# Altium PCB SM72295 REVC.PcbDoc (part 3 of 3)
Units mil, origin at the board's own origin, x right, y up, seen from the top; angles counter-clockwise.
Board outline 8660 x 6340 mil, 6 copper layers (Top Layer, MidLayer1, MidLayer2, MidLayer3, MidLayer4, Bottom Layer), stack 118 mil thick; 253 components, 96 nets, 606 pads, 1472 vias.
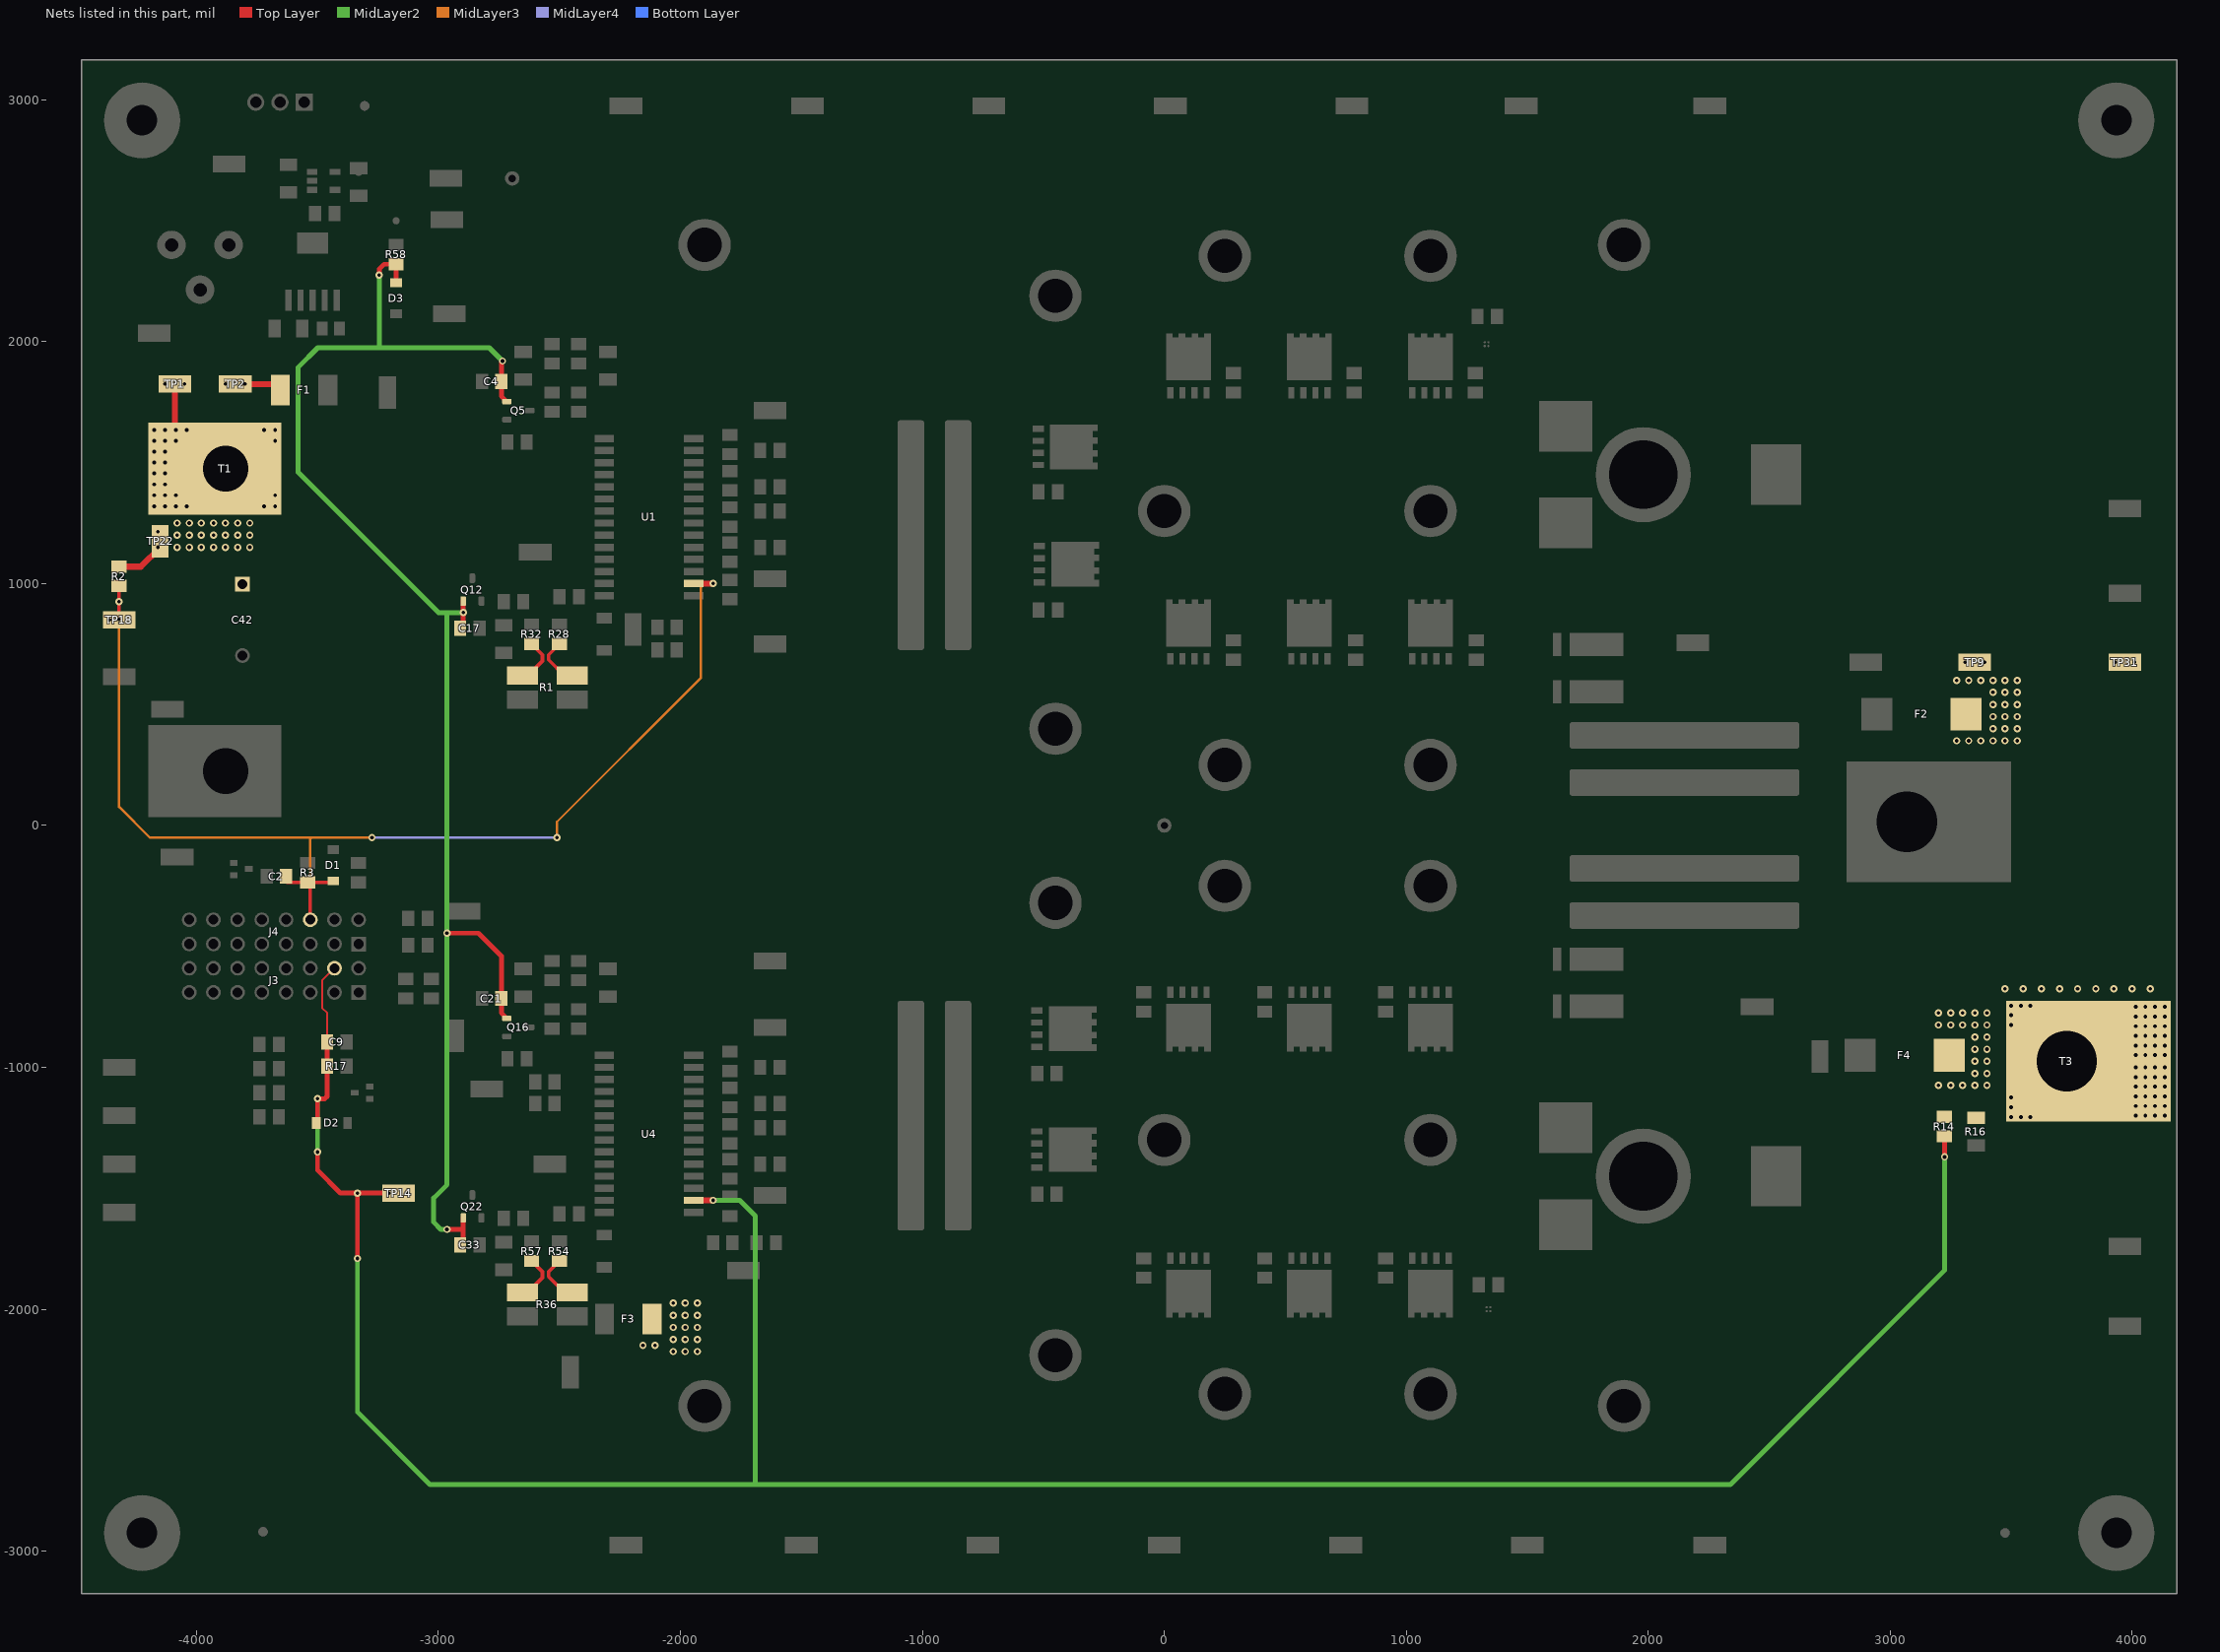
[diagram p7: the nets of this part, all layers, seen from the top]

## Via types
v1: diameter 22, hole 10, Top Layer to Bottom Layer, 518 vias
v2: diameter 30, hole 15, Top Layer to Bottom Layer, 479 vias
v3: diameter 50, hole 28, Top Layer to Bottom Layer, 303 vias
v4: diameter 32, hole 16, Top Layer to Bottom Layer, 172 vias

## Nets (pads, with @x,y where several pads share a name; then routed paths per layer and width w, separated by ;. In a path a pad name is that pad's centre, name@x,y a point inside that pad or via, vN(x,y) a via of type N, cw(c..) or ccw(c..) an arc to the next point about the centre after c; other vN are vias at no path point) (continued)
V12: F2.1 F4.1 R14.2 R16.2 T3.1 TP9.1 TP31.1
  other v2: 3200,-1075 3250,-1075 3300,-1075 3350,-1075 3400,-1075 3350,-1025 3400,-1025 3350,-975 3400,-975 3350,-925 3400,-925 3350,-875 3400,-875 3200,-825 3250,-825 3300,-825 3350,-825 3400,-825 3200,-775 3250,-775 3300,-775 3350,-775 3400,-775 3475,-675 3550,-675 3625,-675 3700,-675 3775,-675 3850,-675 3925,-675 4000,-675 4075,-675 3275,350 3325,350 3375,350 3425,350 3475,350 3525,350 3425,400 3475,400 3525,400 3425,450 3475,450 3525,450 3425,500 3475,500 3525,500 3425,550 3475,550 3525,550 3275,600 3325,600 3375,600 3425,600 3475,600 3525,600 3310,675 3390,675 3930,675 4010,675
  other v4: 3500,-1205 3540,-1205 3580,-1205 4015,-1200 4055,-1200 4095,-1200 4135,-1200 3500,-1165 4015,-1160 4055,-1160 4095,-1160 4135,-1160 3500,-1125 4015,-1120 4055,-1120 4095,-1120 4135,-1120 4015,-1080 4055,-1080 4095,-1080 4135,-1080 4015,-1040 4055,-1040 4095,-1040 4135,-1040 4015,-1000 4055,-1000 4095,-1000 4135,-1000 4015,-950 4055,-950 4095,-950 4135,-950 4015,-910 4055,-910 4095,-910 4135,-910 4015,-870 4055,-870 4095,-870 4135,-870 4015,-830 4055,-830 4095,-830 4135,-830 3500,-825 4015,-790 4055,-790 4095,-790 4135,-790 3500,-785 4015,-750 4055,-750 4095,-750 4135,-750 3500,-745 3540,-745 3580,-745
V12M: C9.1 D2.2 J3.4 R14.1 R17.2 TP14.1 U4.16 | length 11241.4
  Top Layer w8: C9.1@-3460,-865 -3460,-775 -3480.63,-754.37 -3480.63,-640.63 J3.4@-3430,-590
  Top Layer w20: v2(-3500,-1350) -3500,-1425 -3405,-1520 v2(-3335,-1520) ; D2.2@-3500,-1225.53 v2(-3500,-1130) -3470,-1130 -3460,-1120 R17.2@-3460,-995 C9.1@-3460,-895 ; v2(-3335,-1790) v2(-3335,-1520) ; TP14.1@-3165,-1520 -3170,-1520 v2(-3335,-1520) ; v2(3225,-1370.35) R14.1@3225,-1285
  Top Layer w25: U4.16@-1945,-1550 v2(-1865,-1550)
  MidLayer2 w20: v2(-3500,-1350) v2(-3500,-1130) ; v2(-3335,-1790) -3335,-2425 -3035,-2725 -1690,-2725 ; v2(-1865,-1550) -1755,-1550 -1690,-1615 -1690,-2725 ; v2@3224.83,-1370.17 3224.83,-1840.17 2340,-2725 -1690,-2725
  other v2: -3205,-1520 -3125,-1520
V48: C42.1 F1.2 F3.2 R2.2 T1.1 TP1.1 TP2.1 TP22.1 | length 836.3
  Top Layer w20: T1.1@-3920,1435 T1.1@-3880,1475
  Top Layer w25: R2.2@-4330,1070 -4230,1070 -4150,1150 TP22.1@-4150,1175 TP22.1@-4150,1200 ; T1.1@-4090,1495 TP1.1@-4090,1825 ; TP2.1@-3840,1825 F1.2@-3653.43,1825
  other v2: -2030,-2175 -1980,-2175 -1930,-2175 -2155,-2150 -2105,-2150 -2030,-2125 -1980,-2125 -1930,-2125 -2030,-2075 -1980,-2075 -1930,-2075 -2030,-2025 -1980,-2025 -1930,-2025 -2030,-1975 -1980,-1975 -1930,-1975 -4160,1150 -4080,1150 -4030,1150 -3980,1150 -3930,1150 -3880,1150 -3830,1150 -3780,1150 -4080,1200 -4030,1200 -3980,1200 -3930,1200 -3880,1200 -3830,1200 -3780,1200 -4160,1215 -4080,1250 -4030,1250 -3980,1250 -3930,1250 -3880,1250 -3830,1250 -3780,1250 -4130,1825 -4050,1825 -3880,1825 -3800,1825
  other v4: -4175,1320 -4130,1320 -4085,1320 -4040,1320 -3720,1320 -3675,1320 -4175,1365 -4130,1365 -4085,1365 -3675,1365 -4175,1410 -4130,1410 -4175,1455 -4130,1455 -4175,1500 -4130,1500 -4175,1545 -4130,1545 -4175,1590 -4130,1590 -4085,1590 -3675,1590 -4175,1635 -4130,1635 -4085,1635 -4040,1635 -3720,1635 -3675,1635
V48_1_N: R1.3 R32.2 | length 197.2
  Top Layer w15: R1.3@-2653.35,619.21 -2630.79,619.21 -2570,680 -2570,705 R32.2@-2615,750
V48_1_P: R1.4 R28.2 | length 209.2
  Top Layer w15: R28.2@-2500,750 -2545,705 -2545,685 -2479.21,619.21 R1.4@-2446.65,619.21
V48_2_N: R36.3 R57.2 | length 197.2
  Top Layer w15: R36.3@-2653.35,-1930.79 -2630.79,-1930.79 -2570,-1870 -2570,-1845 R57.2@-2615,-1800
V48_2_P: R36.4 R54.2 | length 209.2
  Top Layer w15: R54.2@-2500,-1800 -2545,-1845 -2545,-1865 -2479.21,-1930.79 R36.4@-2446.65,-1930.79
V48M: C2.1 D1.2 J4.6 R2.1 R3.2 TP18.1 U1.16 | length 4960.7
  Top Layer w10: D1.2@-3440.53,-235 D1.2@-3435,-229.47
  Top Layer w15: TP18.1@-4320,850 v2(-4320,925) R2.1@-4320,990 ; C2.1@-3625,-235 R3.2@-3540,-235 D1.2@-3440.53,-235 ; J4.6@-3530,-390 R3.2@-3530,-245
  Top Layer w25: U1.16@-1945,1000 v2(-1865,1000)
  MidLayer3 w10: v2(-4320,925) -4320,76.75 -4193.25,-50 -3525,-50 ; J4.6@-3530,-390 -3530,-55 -3525,-50 ; v2(-3275,-50) -3525,-50 ; v2(-2510,-50) -2510,15 -1915,610 -1915,985 -1900,1000 v2(-1865,1000)
  MidLayer4 w10: v2(-3275,-50) v2(-2510,-50)
  Bottom Layer w8: J4.6@-3530,-390 J4.6@-3517.11,-390
  other v2: -4360,850 -4319.85,851.47
ZERO_BIAS: C4.1 C17.1 C21.1 C33.1 D3.2 Q5.1 Q12.1 Q16.1 Q22.1 R58.2 | length 6331.5
  Top Layer w20: v2(-3245,2275) -3245,2300 -3225,2320 R58.2@-3175,2320 D3.2@-3175,2244.47 ; v2(-2965,-1670) -2902.4,-1670 -2897.4,-1665 ; v2(-2965,-445) -2835,-445 -2740,-540 C21.1@-2740,-715 -2740,-774.84 Q16.1@-2717.24,-797.6 ; C33.1@-2897.4,-1732.4 -2897.4,-1665 ; Q22.1@-2897.4,-1622.24 -2897.4,-1665 ; C17.1@-2897.4,832.6 v2(-2897.4,880) Q12.1@-2897.4,927.76 ; v2(-2735,1920) -2740,1915 C4.1@-2740,1835 -2740,1775.16 Q5.1@-2717.24,1752.4
  MidLayer2 w20: v2(-3245,2275) -3245,1975 ; v2(-2965,-1670) -2990,-1670 -3020,-1640 -3020,-1540 -2965,-1485 v2(-2965,-445) -2965,879 ; v2(-2897.4,880) -3000,880 -3580,1460 -3580,1893.8 -3498.8,1975 -3245,1975 ; v2(-2735,1920) -2790,1975 -3245,1975
pads on no net: FID1.1 FID2.1 FID3.1 FID4.1 FID5.1 FID6.1 H1.1 H2.1 H3.1 H4.1 H9. H10. H11. H12. H13. H14. H15. H16. H17. H18. H19. H20. H21. H22. H23. H24. H25. H26. H27. H28. H50.1 H51.1 H64.0 J2.1 J3.1 J3.3 J3.10 J3.12 J3.13 J3.14 J3.15 J3.16 J4.3 J4.7 J4.8 J4.10 J4.12 J4.15 L1.3 L2.3 U1.4 U1.11 U4.4 U4.11

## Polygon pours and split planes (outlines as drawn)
NetF3_1 on Top Layer "Top Layer-NetF3_1" (solid, remove dead copper, pour order 72): -2515,-1930 -2515,-2160 -2270,-2160 -2270,-1930
GND on Top Layer "Top Layer-GND" (solid, remove dead copper, pour order 111): -4448.96,-3152.54 -4448.96,3192.46 4211.04,3192.46 4211.04,-3152.54
NetC19_2 on Top Layer " Top Layer-Net C18_2" (solid, remove dead copper, pour order 68): -3105,-1920 -2595,-1920 -2595,-2176.5 -3105,-2176.5
NetF1_1 on Top Layer "Top Layer-Net F1_1" (solid, remove dead copper, pour order 74): -3175,1625 -3175,1915 -3535,1915 -3535,1625
NetC1_2 on Top Layer "Top Layer-NetC1_2" (solid, remove dead copper, pour order 61): -2595,625 -2855,625 -2855,400 -2594.84,400
HG2A_N on Top Layer "Top Layer-SWN_2" (solid, remove dead copper, pour order 109): -480,-745 -480,-1625 -136.03,-1810 -35,-1811.33 1550,-1811.33 1550,-1995 2300,-1995 2300,-1400 1520,-1400 1520,-745
NetC19_2 on Top Layer "Top Layer-C18_2" (solid, remove dead copper, pour order 69): -1550,-2680 1525,-2680 1525,-1835 820,-1835 820,-1840 660,-1840 660,-1835 240,-1835 240,-1835.51 98.62,-1835 -125,-1835 -405,-1695 -1550,-1695
NetC1_2 on Top Layer "Top Layer-NETC1_2" (solid, pour order 62): 1525,2675 1525,1830 -40,1835 -450,1710 -1510,1710 -1510,2675
NetC1_2 on Top Layer "Top Layer-NETC1_2" (solid, remove dead copper, pour order 64): -965,660 -1505,660 -1505,2005.69 -1509.31,2010 -970,2010
HG1A_N on Top Layer "Top Layer-SWN_1" (solid, pour order 108): -105,730 -475,955 -480,1695 -70,1820 1300,1810 1550,1810 1550,2000 2300,2000 2300,1375 1525,1375 1525,1200 1525,735
NetC19_2 on Top Layer "Top Layer-NETC18_2" (solid, remove dead copper, pour order 70): -970,-660 -1535,-660 -1540,-655 -1547.58,-662.58 -1547.58,-1665 -1550,-1975 -970,-1975
V48 on Top Layer "Top Layer-V48" (solid, remove dead copper, pour order 88): -4205,1915 -4205,875 -3545,875 -3545,1915
V12 on Top Layer "Top Layer-V2" (solid, remove dead copper, pour order 110): 3550,310 3550,-290 3160,-290 3160,-1235 4150,-1235 4150,725 3240,725 3240,310
V48 on Top Layer "Top Layer-V48" (solid, remove dead copper, pour order 76): -2190.49,-1930 -1910,-1930 -1912.65,-2230 -2190.49,-2230
NetF1_1 on Top Layer "Top Layer-NetF1_1" (solid, remove dead copper, pour order 71): -2509,625 -2255.94,625 -2255.94,390 -2509,390
NetL1_2 on Top Layer "Top Layer-NETL1_2" (solid, remove dead copper, pour order 90): 1550,1355 1550,825 1675,825 1675,670 2300,670 2300,1355
NetC8_2 on Top Layer "Top Layer-NETC7_2" (solid, remove dead copper, pour order 66): 1670,320 1670,625 3035,625 3035,320
NetC24_2 on Top Layer "Top Layer-NETC13_2" (solid, remove dead copper, pour order 67): 1675,-625 1675,-320 2960,-320 2960,-1080 2618.7,-1080 2618.7,-625
NetL2_1 on Top Layer "Top Layer-NETL2_1" (solid, remove dead copper, pour order 92): 1550,-1355 1550,-815 1675,-815 1675,-670 2540,-670 2540,-1185 2300,-1185 2300,-1355
NetL1_2 on MidLayer3 "MidLayer3-NET L1_2" (solid, remove dead copper, pour order 84): 1575,1340 1575,835 2265,835 2265,1340
NetL2_1 on MidLayer3 "MidLayer3-NET L2_1" (solid, pour order 77): 1580,-845 1580,-1335 2260,-1335 2260,-845
NetC19_2 on MidLayer3 "MidLayer3-NetC18_2" (solid, remove dead copper, pour order 133): -50,-1835 -50,-2050 -45,-2055 1220,-2055 1220,-1840 1225,-1835
NetC24_2 on MidLayer3 "MidLayer3-NetC23_2" (solid, remove dead copper, pour order 138): 2960,-320 2960,-1080 2618.7,-1080 2618.7,-625 1670,-625 1670,-325 1675,-320
NetC8_2 on MidLayer3 "MidLayer3-NetC8_2" (solid, remove dead copper, pour order 139): 3035,625 1670,625 1670,320 3035,320
V12 on MidLayer3 "MidLayer3-V12" (solid, remove dead copper, pour order 132): 4185,725 3240,725 3240,310 3550,310 3550,-290 3160,-290 3160,-1230 3155,-1235 4185,-1235
V48 on MidLayer3 "MidLayer3-V48" (solid, remove dead copper, pour order 135): -4155,1300 -3680,1300 -3680,1100 -2555,55 -2555,-1321.83 -1885,-1776.83 -1885,-2205 -2390,-2205 -2390,-1895 -2930,-1895 -2930,-325 -4155,810
NetC19_2 on MidLayer3 "MidLayer3-NetC18_2" (solid, remove dead copper, pour order 136): -3130,-1915 -2580,-1915 -2580,-2475 -2555,-2500 -1455,-2500 -1455,-650 -1130,-650 -1130,-2637.5 -1362.5,-2870 -2750,-2870 -3130,-2660
HG2A_N on MidLayer3 "MidLayer3-SWN2" (solid, remove dead copper, pour order 140): 2300,-1400 1525.47,-1400 1520,-1394.53 1520,-730 -490,-730 -490,-1610 -470,-1625 -140,-1820 1555,-1820 1563.59,-1828.59 1563.59,-1999.22 2298.03,-1999.22 2300,-2001.18
HG1A_N on MidLayer3 "MidLayer3-SWN1" (solid, remove dead copper, pour order 137): 2300,1380.49 2300,2001.18 1551.18,2001.18 1550,2000 1550,1820 -70,1820 -480,1695 -479.88,1677.8 -480,945 -318.68,859.94 -105,730 -85,730 1526.72,736.72 1526.72,1380.49
GND on MidLayer3 "MidLayer3-GND" (solid, remove dead copper, pour order 141): -4500,-3175 -4500,3200 4200,3200 4200,-3175
NetC1_2 on MidLayer3 "MidLayer3-NetC1_2" (solid, remove dead copper, pour order 134): -30,1835 1235,1835 1235,2070 -24.65,2070 -30,2064.65
NetL1_2 on Bottom Layer "Bottom Layer-NET L1_2" (solid, remove dead copper, pour order 150): 1560,1345 1560,825 2270,825 2270,1345
NetL2_1 on Bottom Layer "Bottom Layer-NET L2_1" (solid, pour order 154): 1571.29,-827.51 1571.29,-1333.84 1575.5,-1338.05 2297.49,-1338.05 2297.49,-830.02 2300,-827.51
NetL2_1 on Bottom Layer "Bottom Layer-Net L2_1" (solid, remove dead copper, pour order 151): 1571.29,-825 1571.29,-1338.05 2300,-1338.05 2300,-825
NetC19_2 on Bottom Layer "Bottom Layer-NetC18_2" (solid, remove dead copper, pour order 152): -25,-1836.82 -25,-2050 1222.49,-2050 1225,-2047.49 1222.49,-2044.98 1222.49,-1835
NetC24_2 on Bottom Layer "Bottom Layer-NetC23_2" (solid, remove dead copper, pour order 173): 2960,-320 2960,-1080 2618.7,-1080 2618.7,-625 1650,-625 1650,-345 1675,-320
NetC8_2 on Bottom Layer "Bottom Layer-NetC8_2" (solid, remove dead copper, pour order 153): 3035,625 1660,625 1675,610 1675,325 3030,325 3035,320
V12 on Bottom Layer "Bottom Layer-V12" (solid, remove dead copper, pour order 155): 4185,725 3240,725 3240,310 3550,310 3550,-290 3160,-290 3160,-1235 4185,-1235
HG2A_N on Bottom Layer "Bottom Layer-SWN2" (solid, remove dead copper, pour order 161): 2300,-2001.18 2300,-1400 1525.47,-1400 1525.47,-739.53 1526.14,-730 -489.92,-730 -490.58,-1613.81 -474.39,-1630 -115,-1820 -105,-1825 1555,-1820 1555,-1960 1552.07,-1995.06 1560,-2005 1555,-2010 2305,-2005
HG1A_N on Bottom Layer "Bottom Layer-SWN1" (solid, remove dead copper, pour order 158): 2305,2001.18 1551.18,2001.18 1550,2000 1550.83,1999.17 1550.83,1819.62 -70.82,1819.62 -255,1765 -475,1695 -471.29,952.74 -105,730 1516.89,730 1518.44,728.44 1525,735 1525,1378.38 2308.38,1378.38 2310,1380
NetC19_2 on Bottom Layer "Bottom Layer-NETC18_2" (solid, remove dead copper, pour order 156): -1600,-640 -1100,-640 -1100,-1050 -1600,-1050
NetF1_1 on Bottom Layer "Bottom Layer-NetF1_1" (solid, remove dead copper, pour order 163): -2515.68,625.68 -2515,625 -2285,625 -2285,385 -2285.68,384.32 -2515.68,384.32
NetC1_2 on Bottom Layer "Bottom Layer-NetC1_2" (solid, remove dead copper, pour order 148): -2855,625 -2595,625 -2595,400 -2855,400
V48 on Bottom Layer "Bottom Layer-V48" (solid, remove dead copper, pour order 167): -4200,1665 -4199,1666 -3650,1666 -3650,1125 -4195.08,1125 -4199.9,1129.83
NetF1_1 on Bottom Layer "Bottom Layer-NetF1_1" (solid, remove dead copper, pour order 165): -3480,1915 -3265,1915 -3265,1625 -3265.06,1625.06 -3480,1625
NetC19_2 on Bottom Layer "Bottom Layer-NetC18_2" (solid, remove dead copper, pour order 157): -3105,-2176.5 -2595,-2176.5 -2596.22,-2175.28 -2596.22,-1920 -3103.78,-1920 -3105,-1921.22
V48 on Bottom Layer "Bottom Layer-V48" (solid, remove dead copper, pour order 169): -2165,-1930 -1910,-1930 -1912.41,-1932.41 -1912.41,-2215 -2162.72,-2215 -2165,-2212.72
GND on Bottom Layer "Bottom Layer-GND" (solid, remove dead copper, pour order 177): -4483,-3200 -4483,3200 4160,3200 4160,-3200
NetC1_2 on Bottom Layer "Bottom Layer-NetC1_2" (solid, remove dead copper, pour order 171): -1506,680 -1505,681 -1093,681 -1091,683 -1091,1134 -1502.49,1134 -1505,1136.51
NetC1_2 on Bottom Layer "Bottom Layer-NetC1_2" (solid, pour order 149): -30,2070 -30,1835 1235,1835 1235,2070 -30,2070
GND on MidLayer1 "MidLayer1-GND" (solid, remove dead copper, pour order 121): -4500,-3150 -4500,3175 4200,3175 4200,-3150
NetL1_2 on MidLayer1 "MidLayer1-NET L1_2" (solid, remove dead copper, pour order 80): 1580,1340 1580,830 2260,830 2260,1340
NetL2_1 on MidLayer1 "MidLayer1-NET L2_1" (solid, remove dead copper, pour order 73): 1560,-845 1560,-1330 2255,-1330 2255,-845
NetC19_2 on MidLayer1 "MidLayer1-NetC18_2" (solid, remove dead copper, pour order 112): -25,-1835 -25,-2050 1225,-2050 1225,-1835
NetC24_2 on MidLayer1 "MidLayer1-NetC23_2" (solid, remove dead copper, pour order 118): 2960,-320 2960,-1080 2630,-1080 2625,-1075 2618.7,-1068.7 2618.7,-625 1665,-625 1675,-615 1675,-320
NetC8_2 on MidLayer1 "MidLayer1-NetC8_2" (solid, remove dead copper, pour order 119): 3035,625 1670,625 1670,320 3035,320
V12 on MidLayer1 "MidLayer1-V12" (solid, remove dead copper, pour order 114): 4185,725 3240,725 3240,310 3550,310 3550,-290 3160,-290 3160,-1232.93 3162.07,-1235 4200,-1235
NetC19_2 on MidLayer1 "MidLayer1-NetC18_2" (solid, remove dead copper, pour order 115): -3105,-1920 -2596.22,-1920 -2595,-1921.22 -2595,-2176.5 -3101.5,-2176.5 -3105.66,-2180.66
HG2A_N on MidLayer1 "MidLayer1-SWN2" (solid, remove dead copper, pour order 120): 2305,-2001.18 2300,-1996.18 2300,-1400 1525.47,-1400 1520,-1394.53 1520,-745 -470,-745 -480,-735 -480,-1624.39 -225.61,-1624.39 -40,-1810 -38.67,-1811.33 1550,-1811.33 1550,-1990 1545,-1995
HG1A_N on MidLayer1 "MidLayer1-SWN1" (solid, remove dead copper, pour order 117): 2300,1380.49 2300,2001.18 1551.18,2001.18 1550,2000 1550,1825 -60,1825 -200,1785 -480,1695 -480,955 -465,945 -455,935 -325.31,863.97 -105.47,730.28 1525,730.28 1525,1378.38 1524.8,1378.57 1526.72,1380.49
NetC1_2 on MidLayer1 "MidLayer1-NetC1-2" (solid, remove dead copper, pour order 113): -30,2070 1235,2070 1235,1835 -30,1835
NetL1_2 on MidLayer4 "MidLayer4-NET L1_2" (solid, remove dead copper, pour order 86): 1571.29,1338.05 1571.29,825 2265,825 2265,1338.05
NetL2_1 on MidLayer4 "MidLayer4-NET L2_1" (solid, pour order 78): 1570,-830 1570,-1338.05 2268.71,-1338.05 2268.71,-833.71 2265,-830
NetC19_2 on MidLayer4 "MidLayer4-NetC18_2" (solid, remove dead copper, pour order 144): -25,-1836.82 -25,-2050 -22.49,-2047.49 1225,-2047.49 1225,-1836.82
V12 on MidLayer4 "MidLayer4-V12" (solid, remove dead copper, pour order 143): 4185,725 3240,725 3240,310 3550,310 3550,-290 3160,-290 3160,-1235 4185,-1235
HG1A_N on MidLayer4 "MidLayer4-SWN1" (solid, remove dead copper, pour order 145): 2300,1380.49 2300,2001.18 2298.82,2000 1550,2000 1551.18,1998.82 1550,1825 1537.36,1825 -40,1830 -480,1695 -480,955 -339.03,872.31 -105,730 1526.72,730 1526.72,1380.49
HG2A_N on MidLayer4 "MidLayer4-SWN2" (solid, remove dead copper, pour order 146): 2300,-1400 1525.47,-1400 1525.47,-735.47 1523.7,-733.7 -484.97,-733.7 -490,-1610 -490,-1620 -135,-1810 1534.44,-1810 1545,-2000 1545.78,-1999.22 2300,-1994.03
GND on MidLayer4 "MidLayer4-GND" (solid, remove dead copper, pour order 147): -4500,-3160 -4500,3200 4200,3200 4200,-3160
NetC1_2 on MidLayer4 "MidLayer4-NetC1_2" (solid, remove dead copper, pour order 142): -30,2070 -30,1835 1230,1835 1235,1840 1235,2070 -26.03,2070 -30,2066.03
NetL1_2 on MidLayer2 "MidLayer2-NET L1_2" (solid, remove dead copper, pour order 82): 1569.31,1345 1569.31,815 2305,815 2305,1345
NetL2_1 on MidLayer2 "MidLayer2-NET L2_1" (solid, remove dead copper, pour order 75): 1560,-830 1560,-1335 2267.15,-1335 2267.15,-830
NetC19_2 on MidLayer2 "MidLayer2-NetC18_2" (solid, remove dead copper, pour order 122): -25,-1835 -25,-2050 1225,-2050 1225,-1835
NetC19_2 on MidLayer2 "MidLayer2-NetC18_2" (solid, remove dead copper, pour order 123): -1445,-645 -1445,-945 -1311.45,-1078.55 -1130.25,-1078.55 -1130.25,-658.92 -1130,-645
NetC24_2 on MidLayer2 "MidLayer2-NetC23_2" (solid, remove dead copper, pour order 128): 2960,-320 2960,-1080 2618.7,-1080 2618.7,-625 1660,-625 1670,-615 1670,-325
V12 on MidLayer2 "MidLayer2-V12" (solid, remove dead copper, pour order 125): 4185,725 3240,725 3240,310 3550,310 3550,-290 3160,-290 3162.07,-292.07 3162.07,-1235 4185,-1235
NetC1_2 on MidLayer2 "MidLayer2-NetC1_2" (solid, remove dead copper, pour order 126): -1505,1100 -1115,1100 -1115,495 -1475,90 -2905,90 -2905,650 -2575,650 -2574.61,635.25 -2574.61,373.27 -2572.87,375 -1830,375 -1505,700
HG2A_N on MidLayer2 "MidLayer2-SWN2" (solid, remove dead copper, pour order 130): 2298.97,-1995.06 2300,-1994.03 2300,-1400 1520,-1400 1520,-735 -480,-735 -480,-1625 -285,-1730 -135,-1810 1550,-1811.33 1550,-1990 1551.65,-1994.04 1560,-1995 2300,-1995
HG1A_N on MidLayer2 "MidLayer2-SWN1" (solid, pour order 129): 2300,1380.49 2300,2001.18 1550,2000 1550,1810 -55,1820 -71.26,1819.62 -480,1695 -480,970 -105,730 1518.44,728.44 1526.72,736.72 1526.72,1380.49
GND on MidLayer2 "MidLayer2-GND" (solid, remove dead copper, pour order 131): -4500,-3170 -4500,3200 4200,3200 4200,-3170
NetC1_2 on MidLayer2 "MidLayer2-NetC1_2" (solid, remove dead copper, pour order 124): -30,1835 1235,1835 1235,2070 1225,2060 -30,2060
NetF1_1 on MidLayer2 "MidLayer2-NetF1_1" (solid, remove dead copper, pour order 127): -2255,375 -2255,850 -3080,1675 -3080,1913 -3142.01,1912.99 -3517,1912.99 -3517,1613 -3517.02,1607.06 -2529.59,645.49 -2530,375

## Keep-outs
Keep-Out Layer:
  the board outline again, w10
  text ".Layer_Name" at -4298,-4033.49 h60

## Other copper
Top Layer:
  text ".Layer_Name" at -4298,-4033.49 h60
MidLayer1:
  rectangle net V48: -2183.02,-2230.74 -1905,-1925
  rectangle net NetF3_1: -2510,-2170 -2375,-1930
  rectangle net NetC19_2: -1460,-1055 -1140,-655
  rectangle net NetC1_2: -1455,700 -1150,1110
  rectangle net NetF1_1: -3499,1625.08 -3265,1915
  rectangle net V48: -4125,1100 -3733,1295
  rectangle net NetC1_2: -2853.53,395 -2595,628.53
  rectangle net NetF1_1: -2510,387 -2250,625
  rectangle net NetL1_2: 1675,670 1910,840
  rectangle net NetC8_2: 1675,475 1910,625
  rectangle net NetL2_1: 1660,-850 1925,-670
  rectangle net NetC24_2: 1660,-625 1925,-470
MidLayer2:
  rectangle net V48: -4125,1100 -3733,1305
  rectangle net V48: -2184.75,-2234.46 -1905,-1925
  rectangle net NetF3_1: -2510,-2170 -2365,-1930
  rectangle net NetC19_2: -3129.51,-2185 -2590,-1915.1
  rectangle net NetL1_2: 1655,670 1930,825
  rectangle net NetC8_2: 1655,505 1930,625
  rectangle net NetL2_1: 1660,-840 1930,-670
  rectangle net NetC24_2: 1660,-625 1930,-475
MidLayer3:
  rectangle net NetF1_1: -3499,1620 -3260,1915
  rectangle net NetF1_1: -2508.16,390 -2255.94,631.45
  rectangle net NetC1_2: -2855,395 -2595,625
  rectangle net NetC1_2: -1465,685 -1145,1105
  rectangle net NetF3_1: -2510,-2170 -2375,-1930
  rectangle net NetL1_2: 1670,670 1910,865
  rectangle net NetC8_2: 1670,475 1910,625
  rectangle net NetL2_1: 1670,-865 1915,-665
  rectangle net NetC24_2: 1670,-625 1915,-490
MidLayer4:
  rectangle net V48: -4135,1090 -3720,1310
  rectangle net NetF1_1: -2509,387 -2250,625
  rectangle net NetC1_2: -2855,395 -2595,625
  rectangle net NetC19_2: -1455,-1090 -1145,-640
  rectangle net NetC1_2: -1455,700 -1150,1110
  rectangle net V48: -2175,-2210.91 -1886.92,-1935
  rectangle net NetF3_1: -2500,-2160 -2370,-1930
  rectangle net NetC19_2: -3103.78,-2190 -2595,-1920
  rectangle net NetL2_1: 1660,-840 1935,-670
  rectangle net NetC24_2: 1660,-625 1935,-485
  rectangle net NetL1_2: 1660,670 1925,835
  rectangle net NetC8_2: 1660,470 1925,625
  rectangle net NetC8_2: 2775,305 3065,610
Bottom Layer:
  rectangle net NetL1_2: 1660,670 1925,835
  rectangle net NetC8_2: 1660,470 1925,625
  rectangle net NetL2_1: 1665,-845 1925,-670
  rectangle net NetC24_2: 1665,-625 1925,-470
  rectangle net P2_LOW: -4390,-1235 -4250,-1165
  rectangle net P2_HI: -4390,-1435 -4250,-1365
  rectangle net V48: -4160,1790.06 -4017.33,1860
  rectangle net V48: -3912.67,1789.56 -3768.54,1859.94
  rectangle net NetF1_1: -3245.98,1719.29 -3174.37,1860.44
  rectangle net HG1A_N: -1700,1680.06 -1560,1749.94
  rectangle net NetL1_2: 2115,720 2255,790
  rectangle net NetC8_2: 2830,640 2970,710
  rectangle net V12M: -3235,-1555 -3095,-1485
  rectangle net \O\V\P: -1810,-1880 -1670,-1805
  rectangle net V48M: -4388,812 -4299,884.94
  rectangle net P1_HI: -4390,580.06 -4299.48,652
  rectangle net NetF3_1: -2490,-2330 -2420,-2190
  rectangle net P1_LO: -4190,440 -4050,515
  rectangle net HG2A_N: -1700,-869.94 -1625.49,-800
  rectangle net LG2A: -1700,-595 -1560,-525
  rectangle net 12V: -3935,2700 -3795,2770
  text ".Layer_Name" at -4298,-4033.49 h60

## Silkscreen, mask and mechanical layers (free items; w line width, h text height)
Top Overlay:
  lines w10: -4090,-3060.16 -4090,-3140 -4090,-3145 -3270,-3145 -3270,-1275 ; -4090,-2760 -4090,-320 -3265,-320 -3270,-325 ; -3270.71,-1040 -3270.71,-738.21
  text "SM72295" at 3120,2470 h100
  text "TIDA-00558" at 2975,2300 h100
  text "+48V" at -3575,1400 h100
  text "+" at -3608,1188 h100
  text "-48V" at -3575,185 h100
  text "-12V" at 3025,-400 h100
  text "+12V" at 3615,-1393 h100
  text "2015" at -3100,-3070 h60
  text "TI" at -2824,-3070 h60
  text "©" at -3217,-3073.52 h105
  text ".Layer_Name" at -4298,-4033.49 h60
Bottom Overlay:
  text "MADE IN U.S." at -2755,-3065 h60
  text "UL94V-0" at -1945.5,-3088.5 h60
  text ".Layer_Name" at -4298,-4033.49 h60
Top Paste:
  text ".Layer_Name" at -4298,-4033.49 h60
Bottom Paste:
  text ".Layer_Name" at -4298,-4033.49 h60
Top Solder:
  text ".Layer_Name" at -4298,-4033.49 h60
  text ".Layer_Name" at -4298,-4033.49 h60
Bottom Solder:
  text ".Layer_Name" at -4298,-4033.49 h60
Drill Guide:
  text ".Layer_Name" at -4298,-4033.49 h60
M1 Board Outline:
  the board outline again, w10
  text ".Layer_Name" at -4298,-4033.49 h60
M2 Board Dimensions:
  rectangle: -4750,-3585.5 -4375,-3460.5
  rectangle: -4875,-3460.5 -4750,-3335.5
  lines w7: -4875,-3460.5 -3875,-3460.5 ; -4750,-3585.5 -4750,-3335.5 ; -4625,-3585.5 -4625,-3335.5 ; -4375,-3585.5 -4375,-3335.5 ; -4125,-3585.5 -4125,-3335.5 ; -4875,-3585.5 -4875,-3335.5 -3875,-3335.5 -3875,-3585.5 -4875,-3585.5
  text ".Layer_Name" at -4298,-4033.49 h60
M3 3D STEP Top:
  text ".Layer_Name" at -4298,-4033.49 h60
M4 3D STEP Bottom:
  text ".Layer_Name" at -4298,-4033.49 h60
M5 Assembly Top:
  lines w10: -5167,-4105.17 1433,-4105.17 ; -5167,-3901.83 1435,-3901.83 ; -5167,-3698.5 -5167,-4308.5 -1162,-4308.5 1435,-4308.5 1435,-3698.5 -5166.5,-3698.5 -5166.5,-4308.5 -3591,-4308.5 ; -2702,-4308.5 -2702,-3698.5 ; -1435,-3901.83 -1435,-3698.5 ; -595,-3901.83 -595,-3698.5 ; 27,-4315 27,-4112.17
  lines w20: -2695,-2680 -2687.5,-2687.5
  text "COMPONENTS MARKED 'DNP' SHOULD NOT BE POPULATED." at -3721.5,-3493.5 h60
  text "ASSEMBLY VARIANT:" at -3722,-3609 h60
  text ".VariantName" at -2686,-3609 h60
  text "PCB VIEWED FROM TOP SIDE" at -5103.5,-3830.67 h60
  text "BOARD #:" at -2627,-3830.67 h60
  text ".PRJ_Number" at -2081.5,-3830.67 h60
  text "REV:" at -1237,-3830.67 h60
  text ".PCB_Rev" at -945.5,-3830.67 h60
  text "SVN REV:" at -399,-3830.67 h60
  text ".VersionControl_RevNumber" at 107,-3830.67 h60
  text "IGNORE ->" at -5103.5,-4033.49 h60
  text "PLOT NAME =" at -5103.5,-4239.34 h60
  text ".plot_File_Name" at -4298,-4239.34 h60
  text "GENERATED    :" at -2625,-4239.34 h60
  text ".Print_Date" at -1755.5,-4239.34 h60
  text ".Print_Time" at -1026.5,-4239.34 h60
  text "TEXAS INSTRUMENTS" at 238,-4239.34 h60
M6 Assembly Bottom:
  lines w10: -5167.5,-3902.33 1434.5,-3902.33 ; -5165.5,-4105.67 1434.5,-4105.67 ; -3759.5,-4315.5 -3759.5,-4112.67 ; -3137.5,-3902.33 -3137.5,-3699 ; -2297.5,-3902.33 -2297.5,-3699 ; -1030.5,-4309 -1030.5,-3699 ; -141.5,-4309 1434,-4309 1434,-3699 -5167.5,-3699 -5167.5,-4309 -2570.5,-4309 1434.5,-4309 1434.5,-3699
  text "COMPONENTS MARKED 'DNP' SHOULD NOT BE POPULATED." at 1227,-3493 h60
  text ".VariantName" at 183,-3609 h60
  text "ASSEMBLY VARIANT:" at 1222,-3609 h60
  text ".VersionControl_RevNumber" at -3839.5,-3831.17 h60
  text "SVN REV:" at -3333.5,-3831.17 h60
  text ".PCB_Rev" at -2787,-3831.17 h60
  text "REV:" at -2495.5,-3831.17 h60
  text ".PRJ_Number" at -1651,-3831.17 h60
  text "BOARD #:" at -1105.5,-3831.17 h60
  text "PCB VIEWED FROM BOTTOM SIDE" at 1371,-3831.17 h60
  text "IGNORE ->" at -2327.15,-4033.49 h60
  text "TEXAS INSTRUMENTS" at -3970.5,-4239.84 h60
  text ".Print_Time" at -2706,-4239.84 h60
  text ".Print_Date" at -1977,-4239.84 h60
  text "GENERATED    :" at -1107.5,-4239.84 h60
  text ".plot_File_Name" at 565.5,-4239.84 h60
  text "PLOT NAME =" at 1371,-4239.84 h60
M7 LPKF Text Top:
  lines w20: 2700,-2690 2700,2675 -2695,2675 -2695,-2687.5 2700,-2687.5
M9 Title Sheet:
  drawing of 57 lines, arcs and shapes, not listed
  text "1" at -4135.16,4861.5 h70
  text "2" at -1639.5,4861.5 h70
  text "3" at 849.84,4861.5 h70
  text "4" at 3356.51,4861.5 h70
  text "5" at 5855.5,4861.5 h70
  text "6" at 8360.5,4861.5 h70
  text "A" at -5291.5,3718.5 h70
  text "A" at 9508.5,3718.5 h70
  text "B" at -5291.5,1338.5 h70
  text "B" at 9508.5,1338.5 h70
  text "C" at -5291.5,-1036.5 h70
  text "C" at 9508.5,-1036.5 h70
  text "PROJECT TITLE:" at 6468.5,-2897.5 h45
  text "TIDA-00558(48V-12V Bi-Directional Converter)" at 6518.5,-3030.83 h70
  text "DESIGNED FOR:" at 6468.5,-3198.5 h45
  text "Public Release" at 6518.5,-3338.5 h70
  text "D" at -5291.5,-3406.5 h70
  text "D" at 9508.5,-3406.5 h70
  text "FILE NAME:" at 6468.5,-3498.5 h45
  text ".PCB_File_Name_No_Path" at 6518.5,-3618.5 h70
  text "Texas Instruments (TI) and/or its licensors do not warrant the accuracy or completeness of this specification" at 1499,-3780.34 h45
  text "ENGINEER:" at 6468.5,-3788.5 h45
  text "LAYOUT BY:" at 7973.5,-3788.5 h45
  text "or any information contained therein. TI and/or its licensors do not warrant that this design will meet" at 1454.01,-3893 h45
  text "Steve Brown" at 6518.5,-3943.49 h70
  text "Dee Lim" at 8024,-3943.49 h70
  text "the specifications, will be suitable for your application or fit for any particular purpose, or will operate in" at 1454.01,-4005.67 h45
  text ".Layer_Name" at -4298,-4033.49 h60
  text "ALTIUM DESIGNER VERSION:" at 7973.5,-4098.5 h45
  text "an implementation. TI and/or its licensors do not warrant that the design is production worthy. You should" at 1454.01,-4118.33 h45
  text "completely validate and test your design implementation to confirm the system functionality for your application." at 1499,-4231 h45
  text ".print_Scale" at 6518.5,-4231.83 h70
  text ".Application_BuildNumber" at 8024,-4231.83 h70
  text "1" at -4135.16,-4438.5 h70
  text "2" at -1639.5,-4438.5 h70
  text "3" at 849.84,-4438.5 h70
  text "4" at 3356.51,-4438.5 h70
  text "5" at 5855.5,-4438.5 h70
  text "6" at 8360.5,-4438.5 h70
M10 Fab Notes:
  drawing of 185 lines, arcs and shapes, not listed
  text "DESIGN INFORMATION" at 7506.02,2735 h60
  text "MIN. TRACK WIDTH:" at 6861.46,2555 h60
  text "8" at 7957.7,2555 h60
  text "MIL" at 8112.46,2555 h60
  text "6.5" at 7890,2435 h60
  text "MIN. CLEARANCE:" at 6861.46,2423 h60
  text "Mil" at 8112.46,2423 h60
  text "MIN. VIA PAD SIZE:" at 6861.46,2291 h60
  text "24" at 7927.71,2291 h60
  text "MIL" at 8112.46,2291 h60
  text "0.05mm (2MIL)" at 7556.46,2149.29 h60
  text "MINIMUM ANNULAR RING" at 6532.23,2145 h60
  text "EXTERNAL" at 8264.46,2145 h60
  text "PER" at 6732.23,2027 h60
  text "IPC-D-275 CLASS 2 LEVEL C" at 6952.23,2027 h60
  text "MIL, HOLES" at 8440.46,1914.71 h60
  text "+/-" at 8048,1914 h60
  text "+/-" at 8902,1914 h60
  text "REGISTRATION TOLERANCES:" at 6532.23,1909 h60
  text "METAL" at 7732,1909 h60
  text "5" at 8308.2,1909 h60
  text "3" at 9141.2,1909 h60
  text "MIL" at 9257.46,1909 h60
  text "MATERIAL:" at 6457.46,1699.54 h60
  text "FR-4 High Tg" at 7443.9,1559.21 h60
  text "FR-408" at 6878.46,1550.64 h60
  text "OTHER" at 8366.46,1550.64 h60
  text "FR4" at 8915,1400 h60
  text "62 MIL (1.6mm) +/-10%" at 7198.56,1387.92 h60
  text "THICKNESS:" at 6532.23,1383.64 h60
  text "X" at 7070.4,1383.64 h60
  text "OTHER" at 8483.46,1383.64 h60
  text "X" at 8350,1370 h60
  text "TOLERANCE:" at 6532.23,1225.64 h60
  text "X" at 7371.53,1225.64 h60
  text "ANSI IPC-6012 TYPE 3 CLASS 2" at 7558.48,1225.64 h60
  text "OTHER +/-" at 7558.46,1069.64 h60
  text "BOW & TWIST:" at 6532.23,912.64 h60
  text "X" at 7371.53,912.64 h60
  text "ANSI IPC-6012 TYPE 3 CLASS 2" at 7558.48,912.64 h60
  text "OTHER +/-" at 7558.46,754.13 h60
  text "DRILLING:" at 6457.46,615.64 h60
  text "REFERENCE:" at 6532.23,498.64 h60
  text "X" at 7180.46,498.64 h60
  text "AS SHOWN" at 7367.46,498.64 h60
  text "X" at 8081.46,498.64 h60
  text "NC_DRILL FILES" at 8218.46,498.64 h60
  text "PTH MIN COPPER THICKNESS:" at 6532.23,340.64 h60
  text "X" at 7882.46,340.64 h60
  text "1MIL" at 8019.46,340.64 h60
  text "OTHER" at 8516.46,340.64 h60
  text "BOARD FINISH:" at 6457.46,181.64 h60
  text "SILKSCREEN:" at 6612.68,63.64 h60
  text "X" at 7561.46,63.64 h60
  text "TOP" at 7687.46,63.64 h60
  text "X" at 8071.46,63.64 h60
  text "BOTTOM" at 8198.46,63.64 h60
  text "SILKSCREEN COLOR:" at 6612.68,-103.36 h60
  text "X" at 7560.42,-103.36 h60
  text "WHITE" at 7687.46,-103.36 h60
  text "OTHER" at 8198.46,-103.36 h60
  text "SOLDER RESIST COLOR:" at 6612.68,-273.36 h60
  text "X" at 7180.42,-432.56 h60
  text "GREEN" at 7307.46,-432.56 h60
  text "BLUE" at 7898.46,-432.56 h60
  text "OTHER" at 8436.46,-432.56 h60
  text "IMMERSION GOLD (ENIG)" at 7518.46,-621.08 h60
  text "ENEPIG" at 8856,-624.36 h60
  text "SURFACE FINISH:" at 6457.46,-625.36 h60
  text "HASL" at 8605,-770 h60
  text "IMM. TIN/SILVER OR EQUIV" at 6787,-782.36 h60
  text "OTHER" at 8218.46,-782.36 h60
  text "X" at 8035,-785 h60
  text "X" at 7315,-960 h60
  text "ARRAY/PANEL:" at 6457.46,-961.36 h60
  text "CUT AND TRIM PER MECH LAYER 1" at 7518.46,-965.65 h60
  text "N.C. ROUTE" at 7518.46,-1117.36 h60
  text "V. SCORE" at 8384.46,-1117.36 h60
  text "CERTIFICATION:" at 6457.46,-1254.36 h60
  text "MATERIALS AND WORKMANSHIP FOR ALL PCBS" at 7182.46,-1254.36 h60
  text "TO MEET OR EXCEED THE REQUIREMENTS OF:" at 7182.46,-1352.36 h60
  text "X" at 6808.96,-1488.87 h60
  text "ANSI IPC-A-600F CLASS ->" at 6947.96,-1488.87 h60
  text "X" at 8587.02,-1488.87 h60
  text "2" at 8705.96,-1488.86 h60
  text "1" at 8390.96,-1490.36 h60
  text "3" at 9059.96,-1490.36 h60
  text "X" at 6811.02,-1648.36 h60
  text "UL 94V-0" at 6947.96,-1648.36 h60
  text "X" at 7623.02,-1648.36 h60
  text "RoHS" at 7759.96,-1648.36 h60
  text "OTHER" at 8404.36,-1648.36 h60
  text "PER ORDER" at 8801.42,-1648.36 h60
  text "ADDITIONAL REQUIREMENTS:" at 6457.46,-1789.36 h60
  text "MICROSECTION:" at 6532.23,-1904.36 h60
  text "YES" at 7437.96,-1904.36 h60
  text "REQUIRED" at 8299.46,-2060.51 h60
  text "BARE BOARD ELEC. TEST:" at 6532.23,-2063.36 h60
  text "NONE" at 7837.96,-2063.36 h60
  text "X" at 8172.46,-2063.36 h60
  text "PER ORDER" at 8891.46,-2063.36 h60
  text "MANUFACTURER'S UL:" at 6532.23,-2220.36 h60
  text "RAIL" at 7697.96,-2224.65 h60
  text "METAL" at 8189.77,-2224.65 h60
  text "X" at 8565,-2225 h60
  text "SILK" at 8701.46,-2224.65 h60
  text ".Layer_Name" at -4298,-4033.49 h60
M11 Gerber Information:
  lines w10: -5167,-4105.17 1433,-4105.17 ; -5167,-3901.83 1435,-3901.83 ; -5167,-3698.5 -5167,-4308.5 -1162,-4308.5 1435,-4308.5 1435,-3698.5 -5166.5,-3698.5 -5166.5,-4308.5 -3591,-4308.5 ; -2702,-4308.5 -2702,-3698.5 ; -1435,-3901.83 -1435,-3698.5 ; -595,-3901.83 -595,-3698.5 ; 27,-4315 27,-4112.17
  text "ALL ARTWORK VIEWED FROM TOP SIDE" at -5103.5,-3830.67 h60
  text "BOARD #:" at -2627,-3830.67 h60
  text ".PRJ_Number" at -2081.5,-3830.67 h60
  text "REV:" at -1237,-3830.67 h60
  text ".PCB_Rev" at -945.5,-3830.67 h60
  text "SVN REV:" at -399,-3830.67 h60
  text ".VersionControl_RevNumber" at 107,-3830.67 h60
  text "LAYER NAME =" at -5103.5,-4033.49 h60
  text "PLOT NAME =" at -5103.5,-4239.34 h60
  text ".plot_File_Name" at -4298,-4239.34 h60
  text "GENERATED    :" at -2625,-4239.34 h60
  text ".Print_Date" at -1755.5,-4239.34 h60
  text ".Print_Time" at -1026.5,-4239.34 h60
  text "TEXAS INSTRUMENTS" at 238,-4239.34 h60
M12 Stackup:
  text ".Layer_Name" at -4298,-4033.49 h60
M13 Component Bodies Top:
  text ".Layer_Name" at -4298,-4033.49 h60
M14 Component Bodies Bottom:
  text ".Layer_Name" at -4298,-4033.49 h60
M15 Courtyards Top:
  text ".Layer_Name" at -4298,-4033.49 h60
M16 Courtyards Bottom:
  text ".Layer_Name" at -4298,-4033.49 h60
Drill Drawing:
  text ".legend" at 4470,-915 h60
  text "Drill Table" at 4495,-1045 h60
  text ".Layer_Name" at -4298,-4033.49 h60

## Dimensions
-4875,-3585.5 to -3875,-3585.5 on M2 Board Dimensions
-4475,-3175 to 4185,-3175 on M2 Board Dimensions
-4475,-3175 to -4475,3165 on M2 Board Dimensions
